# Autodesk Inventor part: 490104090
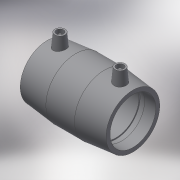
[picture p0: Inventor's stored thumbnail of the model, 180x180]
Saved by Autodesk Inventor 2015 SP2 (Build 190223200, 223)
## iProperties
Created: 2017-06
Part Number: 490104090
Material: Generic
Description: PLASSON COUPLER 90-90
Document SubType Name: Modeling
Designer: KIM
Mass: 425.188 g
Surface Area: 1017.24 cm^2
Volume: 425.188 cm^3
Density: 1 g/cm^3
Appearance: Default
Author: KIM
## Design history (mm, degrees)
derived "490104.ipt"
feature "Solid1::490104.ipt"
tag "TaggingFeature1"
body "Solid1"
other parameters: "d0" = 148, "d2" = 112, "d3" = 73, "d4" = 49.33333, "d5" = 100.8, "d6" = 85.5, "d8" = 168 deg, "d10" = 29.2, "d11" = 9.73333, "d13" = 148, "d14" = 17.6296, "d15" = 73, "d16" = 73, "d17" = 85.5, "d19" = 3.52592, "d20" = 168 deg, "d22" = 105.28, "d23" = 112, "d24" = 102.1216, "d25" = 135 deg, "d26" = 59.2, "d27" = 135 deg, "d29" = 71, "d30" = 14, "d31" = 51.8, "d34" = 5 deg, "d35" = 15, "d39" = 5 deg, "d41" = 4, "d42" = 14, "d43" = 0, "d45" = 4, "d46" = 14, "d47" = 0, "d48" = 3, "d49" = 0, "d50" = 3, "d51" = 0, "d52" = 21.17, "d53" = 5.2925, "L_" = 148, "L_1" = 73, "D_" = 112, "A_" = 71, "d_2" = 12
